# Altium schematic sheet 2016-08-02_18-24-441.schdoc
size 459 x 220 mm; SheetNumber: 1; SheetTotal: 1
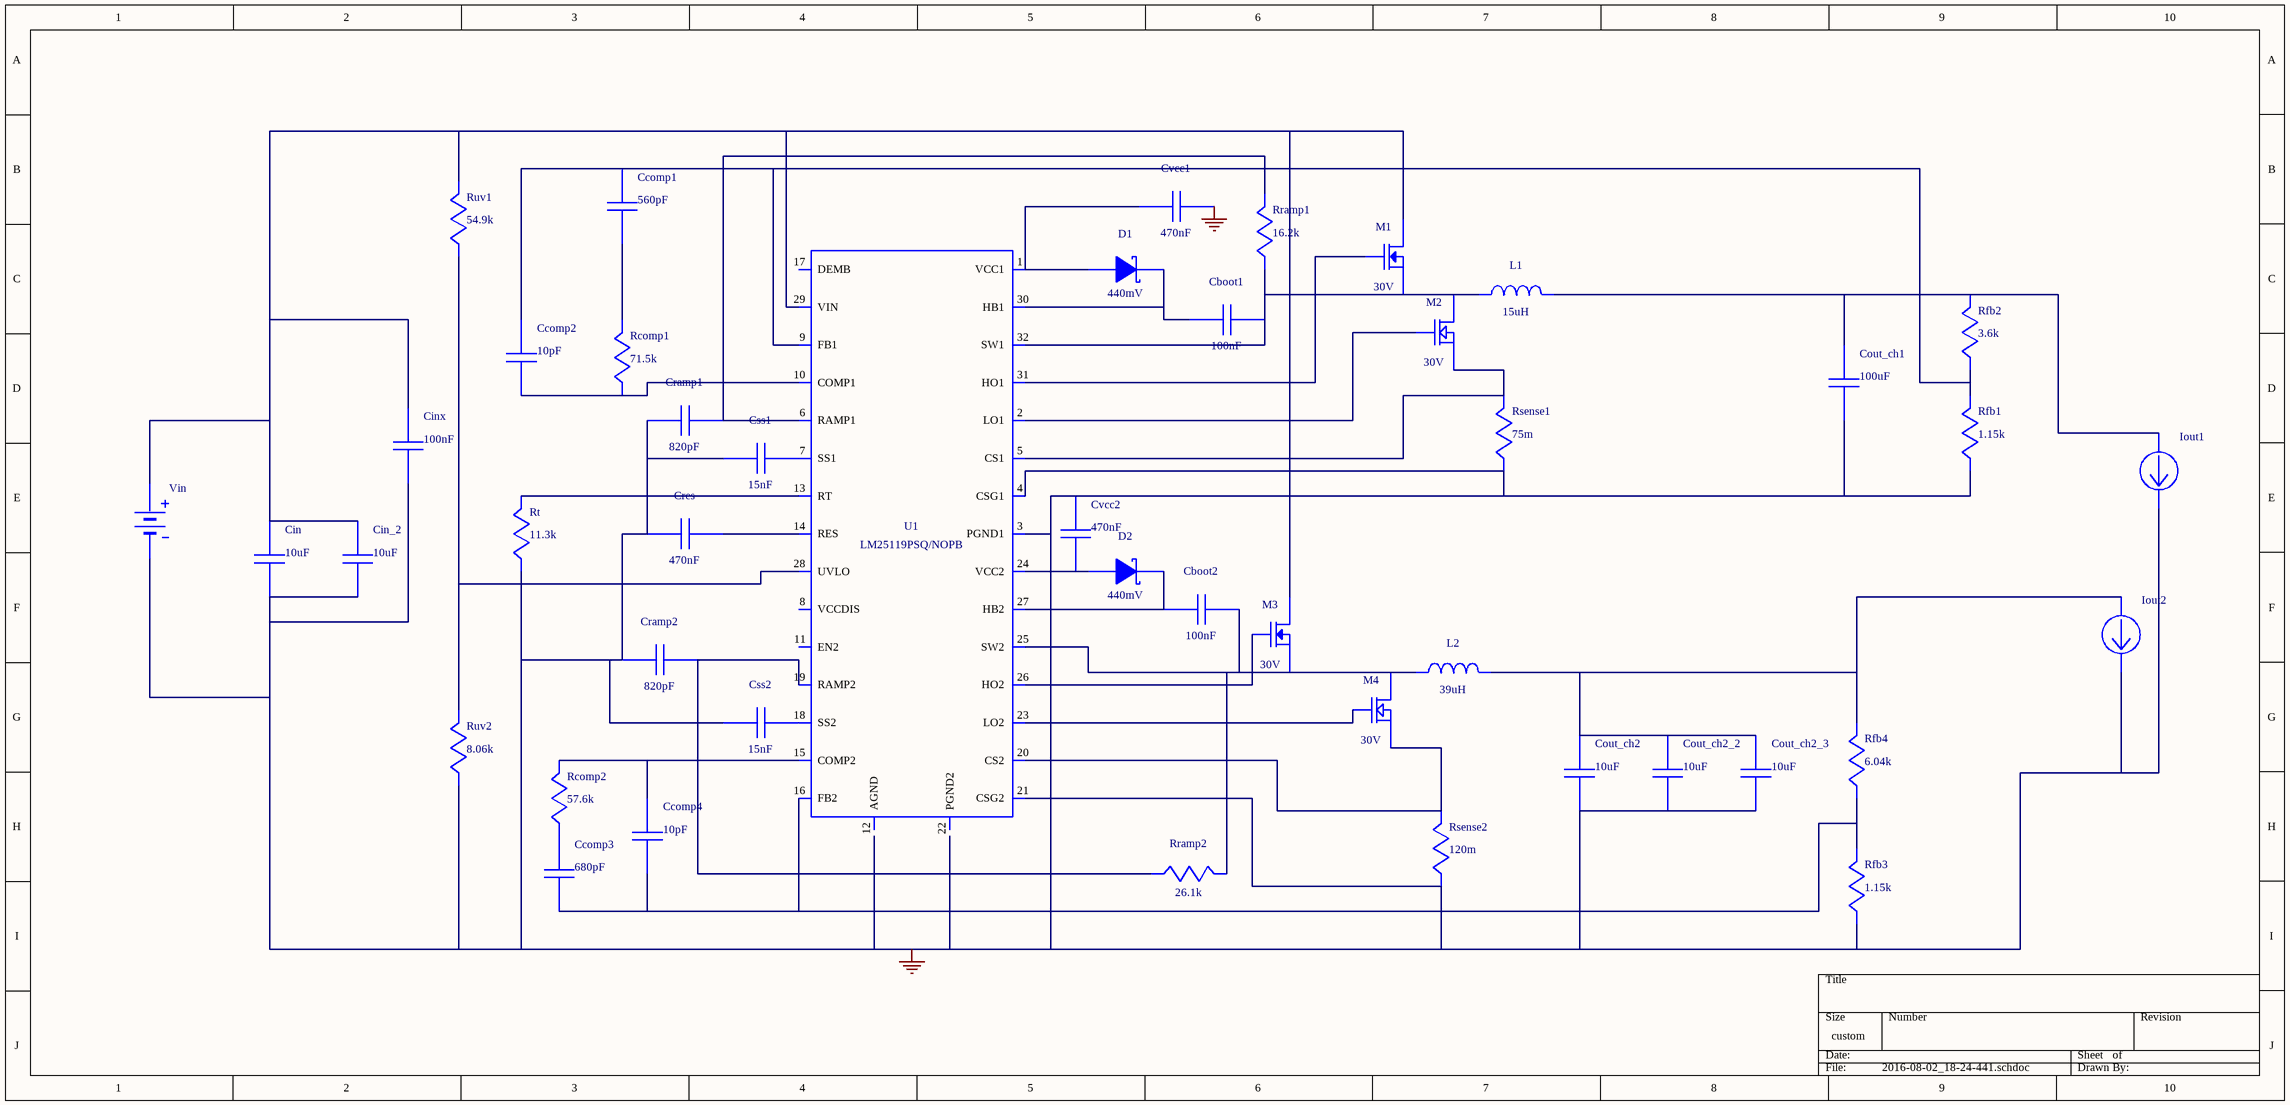
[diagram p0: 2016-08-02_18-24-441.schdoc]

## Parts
Cboot1  value 100nF  (hidden comment: GRM155R61A104KA01D)
Cboot2  value 100nF  (hidden comment: GRM155R61A104KA01D)
Ccomp1  value 560pF  (hidden comment: CC0805KRX7R9BB561)
Ccomp2  value 10pF  (hidden comment: C0805C100K5GACTU)
Ccomp3  value 680pF  (hidden comment: CC0805KRX7R9BB681)
Ccomp4  value 10pF  (hidden comment: C0805C100K5GACTU)
Cin  value 10uF  (hidden comment: GRM21BR61C106KE15L)
Cin_2  value 10uF  (hidden comment: GRM21BR61C106KE15L)
Cinx  value 100nF  (hidden comment: 08053C104KAT2A)
Cout_ch1  value 100uF  (hidden comment: GRM31CD80G107ME39L)
Cout_ch2  value 10uF  (hidden comment: GRM188R60J106ME47D)
Cout_ch2_2  value 10uF  (hidden comment: GRM188R60J106ME47D)
Cout_ch2_3  value 10uF  (hidden comment: GRM188R60J106ME47D)
Cramp1  value 820pF  (hidden comment: CC0805KRX7R9BB821)
Cramp2  value 820pF  (hidden comment: CC0805KRX7R9BB821)
Cres  value 470nF  (hidden comment: GRM155C80J474KE19D)
Css1  value 15nF  (hidden comment: CC0805KRX7R9BB153)
Css2  value 15nF  (hidden comment: CC0805KRX7R9BB153)
Cvcc1  value 470nF  (hidden comment: GRM155R61A474KE15D)
Cvcc2  value 470nF  (hidden comment: GRM155R61A474KE15D)
D1  value 440mV  (hidden comment: CD0603-B0130L)
D2  value 440mV  (hidden comment: CD0603-B0130L)
Iout1  WB_CURRENT_LOAD  (value not drawn)
Iout2  WB_CURRENT_LOAD  (value not drawn)
L1  value 15uH  (hidden comment: SRN6045-150M)
L2  value 39uH  (hidden comment: SDR0604-390KL)
M1  value 30V  (hidden comment: CSD17308Q3)
M2  value 30V  (hidden comment: CSD17579Q3A)
M3  value 30V  (hidden comment: CSD17308Q3)
M4  value 30V  (hidden comment: CSD17579Q3A)
Rcomp1  value 71.5k  (hidden comment: CRCW040271K5FKED)
Rcomp2  value 57.6k  (hidden comment: CRCW040257K6FKED)
Rfb1  value 1.15k  (hidden comment: CRCW04021K15FKED)
Rfb2  value 3.6k  (hidden comment: RC0603FR-073K6L)
Rfb3  value 1.15k  (hidden comment: CRCW04021K15FKED)
Rfb4  value 6.04k  (hidden comment: CRCW04026K04FKED)
Rramp1  value 16.2k  (hidden comment: CRCW040216K2FKED)
Rramp2  value 26.1k  (hidden comment: CRCW040226K1FKED)
Rsense1  value 75m  (hidden comment: ERJ-L03UF75MV)
Rsense2  value 120m  (hidden comment: ERJ-3RSFR12V)
Rt  value 11.3k  (hidden comment: CRCW040211K3FKED)
Ruv1  value 54.9k  (hidden comment: CRCW040254K9FKED)
Ruv2  value 8.06k  (hidden comment: CRCW04028K06FKED)
U1  LM25119PSQ/NOPB
Vin  WB_BATTERY  (value not drawn)

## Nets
0: Cin.2 Cin_2.2 Cinx.2 Cout_ch1.2 Cout_ch2.2 Cout_ch2_2.2 Cout_ch2_3.2 Cramp1.2 Cramp2.2 Cres.2 Css1.2 Css2.2 Cvcc1.2 Cvcc2.2 Iout1.2(-) Iout2.2(-) Rfb1.2 Rfb3.2 Rsense1.2 Rsense2.2 Rt.2 Ruv2.2 U1.3(PGND1) U1.4(CSG1) U1.21(CSG2) U1.33(EP) Vin.2(-)
NetCboot1_1: Cboot1.1 L1.1 M1.1(Source) M1.2(Source) M1.3(Source) M2.5(Drain) M2.6(Drain) M2.7(Drain) M2.8(Drain) M2.9(Drain) Rramp1.2 U1.32(SW1)
NetCboot1_2: Cboot1.2 D1.1(K) U1.30(HB1)
NetCboot2_1: Cboot2.1 L2.1 M3.1(Source) M3.2(Source) M3.3(Source) M4.5(Drain) M4.6(Drain) M4.7(Drain) M4.8(Drain) M4.9(Drain) Rramp2.1 U1.25(SW2)
NetCboot2_2: Cboot2.2 D2.1(K) U1.27(HB2)
NetCcomp1_1: Ccomp1.1 Rcomp1.1
NetCcomp1_2: Ccomp1.2 Ccomp2.2 Rfb1.1 Rfb2.2 U1.9(FB1)
NetCcomp2_1: Ccomp2.1 Rcomp1.2 U1.10(COMP1)
NetCcomp3_1: Ccomp3.1 Rcomp2.2
NetCcomp3_2: Ccomp3.2 Ccomp4.2 Rfb3.1 Rfb4.2 U1.16(FB2)
NetCcomp4_1: Ccomp4.1 Rcomp2.1 U1.15(COMP2)
NetCin_1: Cin.1 Cin_2.1 Cinx.1 M1.5(Drain) M1.6(Drain) M1.7(Drain) M1.8(Drain) M1.9(Drain) M3.5(Drain) M3.6(Drain) M3.7(Drain) M3.8(Drain) M3.9(Drain) Ruv1.1 U1.29(VIN) Vin.1(+)
NetCout_ch1_1: Cout_ch1.1 Iout1.1(+) L1.2 Rfb2.1
NetCout_ch2_1: Cout_ch2.1 Cout_ch2_2.1 Cout_ch2_3.1 Iout2.1(+) L2.2 Rfb4.1
NetCramp1_1: Cramp1.1 Rramp1.1 U1.6(RAMP1)
NetCramp2_1: Cramp2.1 Rramp2.2 U1.19(RAMP2)
NetCres_1: Cres.1 U1.14(RES)
NetCss1_1: Css1.1 U1.7(SS1)
NetCss2_1: Css2.1 U1.18(SS2)
NetCvcc1_1: Cvcc1.1 D1.2(A) U1.1(VCC1)
NetCvcc2_1: Cvcc2.1 D2.2(A) U1.24(VCC2)
NetM1_4: M1.4(Gate) U1.31(HO1)
NetM2_1: M2.1(Source) M2.2(Source) M2.3(Source) Rsense1.1 U1.5(CS1)
NetM2_4: M2.4(Gate) U1.2(LO1)
NetM3_4: M3.4(Gate) U1.26(HO2)
NetM4_1: M4.1(Source) M4.2(Source) M4.3(Source) Rsense2.1 U1.20(CS2)
NetM4_4: M4.4(Gate) U1.23(LO2)
NetRt_1: Rt.1 U1.13(RT)
NetRuv1_2: Ruv1.2 Ruv2.1 U1.28(UVLO)

Not connected (* = marked no-connect by the designer): U1 8(VCCDIS) 11(EN2) 12(AGND) 17(DEMB) 22(PGND2)

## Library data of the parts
Cboot1 Cboot2 = GRM155R61A104KA01D: GRM155R61A104KA0; Manufacturer Name: MuRata
Ccomp1 = CC0805KRX7R9BB561: CC0805KRX7R9BB56; Manufacturer Name: Yageo America
Ccomp2 Ccomp4 = C0805C100K5GACTU: Manufacturer Name: Kemet
Ccomp3 = CC0805KRX7R9BB681: CC0805KRX7R9BB68; Manufacturer Name: Yageo America
Cin Cin_2 = GRM21BR61C106KE15L: GRM21BR61C106KE1; Manufacturer Name: MuRata
Cinx = 08053C104KAT2A: Manufacturer Name: AVX
Cout_ch1 = GRM31CD80G107ME39L: GRM31CD80G107ME3; Manufacturer Name: MuRata
Cout_ch2 Cout_ch2_2 Cout_ch2_3 = GRM188R60J106ME47D: GRM188R60J106ME4; Manufacturer Name: MuRata
Cramp1 Cramp2 = CC0805KRX7R9BB821: CC0805KRX7R9BB82; Manufacturer Name: Yageo America
Cres = GRM155C80J474KE19D: GRM155C80J474KE1; Manufacturer Name: MuRata
Css1 Css2 = CC0805KRX7R9BB153: CC0805KRX7R9BB15; Manufacturer Name: Yageo America
Cvcc1 Cvcc2 = GRM155R61A474KE15D: GRM155R61A474KE1; Manufacturer Name: MuRata
D1 D2 = CD0603-B0130L: Manufacturer Name: Bourns
L1 = SRN6045-150M: Manufacturer Name: Bourns
L2 = SDR0604-390KL: Manufacturer Name: Bourns
M1 M3 = CSD17308Q3: Manufacturer Name: Texas Instruments
M2 M4 = CSD17579Q3A: Manufacturer Name: Texas Instruments
Rcomp1 = CRCW040271K5FKED: Manufacturer Name: Vishay-Dale
Rcomp2 = CRCW040257K6FKED: Manufacturer Name: Vishay-Dale
Rfb1 Rfb3 = CRCW04021K15FKED: Manufacturer Name: Vishay-Dale
Rfb2 = RC0603FR-073K6L: Manufacturer Name: Yageo America
Rfb4 = CRCW04026K04FKED: Manufacturer Name: Vishay-Dale
Rramp1 = CRCW040216K2FKED: Manufacturer Name: Vishay-Dale
Rramp2 = CRCW040226K1FKED: Manufacturer Name: Vishay-Dale
Rsense1 = ERJ-L03UF75MV: Manufacturer Name: Panasonic
Rsense2 = ERJ-3RSFR12V: Manufacturer Name: Panasonic
Rt = CRCW040211K3FKED: Manufacturer Name: Vishay-Dale
Ruv1 = CRCW040254K9FKED: Manufacturer Name: Vishay-Dale
Ruv2 = CRCW04028K06FKED: Manufacturer Name: Vishay-Dale
U1 = LM25119PSQ/NOPB: Manufacturer Name: Texas Instruments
